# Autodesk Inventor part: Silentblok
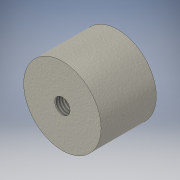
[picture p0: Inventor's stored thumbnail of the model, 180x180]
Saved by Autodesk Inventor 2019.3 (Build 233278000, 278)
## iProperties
Created: 2019-02
Part Number: Silentblok
Material: Pryž
Document SubType Name: Modeling
Designer: B-hon
Density: 0.93 g/cm^3
Appearance: Ocel – litá
Author: B-hon
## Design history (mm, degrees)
sketch "Náčrt1"
  geometry: C1 r 21 at (0, 0); 1 further point
  constraints: 1 centre point, 1 coincident
  dimensions: "d0" = 42 diameter of C1
extrude "Vysunutí1" new body sketch "Náčrt1" distance "d1" = 30; taper "d2" = 0 deg
sketch "Náčrt2"
  geometry: C1 r 21 at (0, 0) reference; 2 further points
  constraints: 1 coincident
hole "Díra1" sketch "Náčrt2" at (0, 0) diameter "d3" = 8.376; stored, may be unused: countersink angle "d7" = 90 deg, drill point angle "d9" = 118 deg; dims "d4" = 20, "d5" = 4, "d6" = 2, "d8" = 27.3
node "Těleso1"
